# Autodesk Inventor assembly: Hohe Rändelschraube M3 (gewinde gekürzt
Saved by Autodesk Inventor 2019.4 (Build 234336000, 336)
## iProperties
Created: 2021-06
Part Number: Hohe Rändelschraube M3 (gewinde gekürzt
Document SubType Name: Assembly
Designer: Administrator
Title: Hohe Rändelschraube M3 (gewinde gekürzt v3
Author: Administrator
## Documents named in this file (2)
- c:\worker\convert-fusion-r04\tmp\job-1\39\output\files\e1e84fd7-b652-4e3d-a1c7-f0a54bbc30a7\Hohe Rändelschraube M3 (gewinde gekürzt v3.iam
- c:\worker\convert-fusion-r04\tmp\job-1\39\output\files\e1e84fd7-b652-4e3d-a1c7-f0a54bbc30a7\_Knurled screw DIN 464-M3-6-ZB.ipt
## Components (1 placed, 1 different names)
1. _Knurled screw DIN 464-M3-6-ZB:1
